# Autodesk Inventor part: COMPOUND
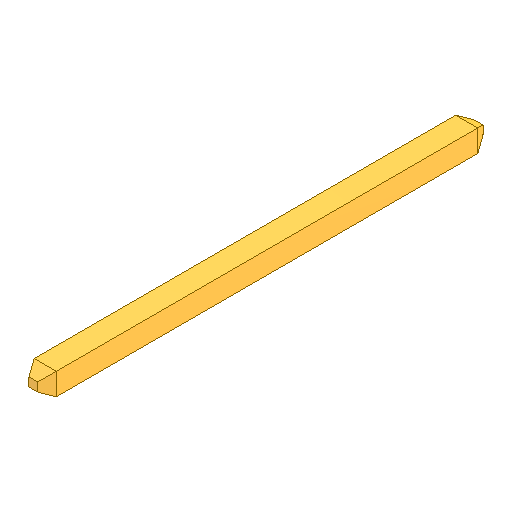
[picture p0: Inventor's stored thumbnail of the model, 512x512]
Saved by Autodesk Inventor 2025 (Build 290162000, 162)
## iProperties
Created: 2025-05
Part Number: COMPOUND
Material: Generico
Document SubType Name: Modeling
Designer: R5800u
Density: 1 g/cm^3
Appearance: Default
Author: R5800u
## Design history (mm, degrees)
feature "Base1"
node "Solido1"
